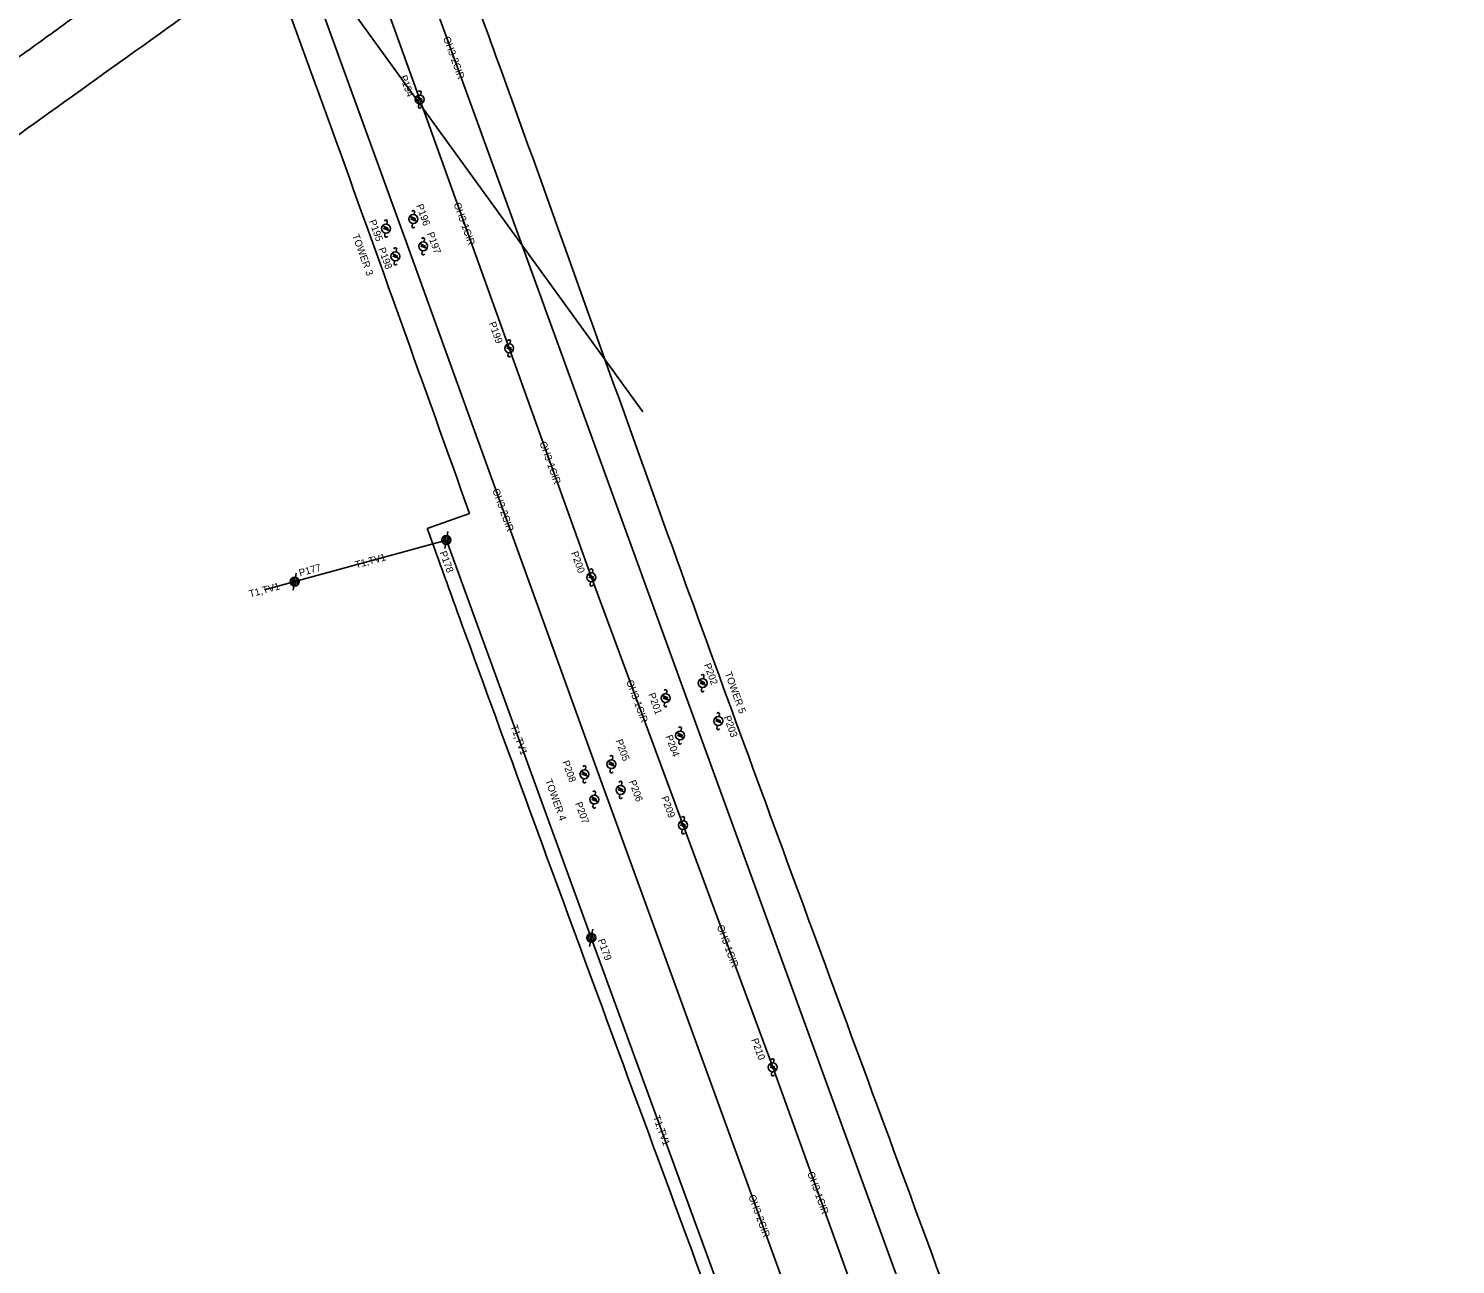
# Model space of a CAD drawing. Extents: x 1991878 to 2008544, y 770238 to 1141211.
# Drawn here: x 2004177 to 2004972, y 1138328 to 1139018 of the extents above; entities that cross this region are included whole.
import ezdxf

# ---------------------------------------------------------------- set-up
doc = ezdxf.new("R2010")
doc.units = 0
for name, color, linetype in [('RD_EX_SU_Ovhd', 7, 'Continuous'), ('RD_EX_SU_Pole', 7, 'Continuous'), ('RD_EX_SU_SwpLmt', 7, 'Continuous'), ('RD_EX_SU_TX_Ovhd', 7, 'Continuous'), ('RD_EX_SU_TX_Pole', 7, 'Continuous'), ('RD_HC_Cl', 7, 'Continuous')]:
    doc.layers.add(name, color=color, linetype=linetype)

msp = doc.modelspace()

# ---------------------------------------------------------------- linework, layer by layer
at = {"layer": 'RD_EX_SU_Ovhd'}
for p, q in [((2004386.44, 1138901.38), (2004185.77, 1139454.37)), ((2004282.2, 1139364.47), (2004545.93, 1138638.38)), ((2004354.72, 1139090.45), (2004394.96, 1138978.21)), ((2004394.96, 1138978.21), (2004444.8, 1138839.43)), ((2004496.56, 1138596.92), (2004386.44, 1138901.38)), ((2004444.8, 1138839.43), (2004490.68, 1138711.64)), ((2004325.26, 1138709.33), (2004409.79, 1138732.48)), ((2004409.79, 1138732.48), (2004490.53, 1138510.63)), ((2004308.35, 1138704.69), (2004325.26, 1138709.33)), ((2004490.68, 1138711.64), (2004541.77, 1138573.46)), ((2004545.93, 1138638.38), (2004819.62, 1137885.66)), ((2004672.08, 1138113.86), (2004496.56, 1138596.92)), ((2004541.77, 1138573.46), (2004591.73, 1138438.41)), ((2004490.53, 1138510.63), (2004568.62, 1138296.79)), ((2004591.73, 1138438.41), (2004642.44, 1138298.1))]:
    msp.add_line(p, q, dxfattribs=at)
at = {"layer": 'RD_EX_SU_Pole'}
for p, q in [((2004395.41, 1138980.66), (2004395.67, 1138982.14)), ((2004394.24, 1138974.27), (2004394.51, 1138975.75)), ((2004391.79, 1138913.93), (2004392.06, 1138915.41)), ((2004376.57, 1138908.67), (2004376.84, 1138910.15)), ((2004390.63, 1138907.54), (2004390.89, 1138909.02)), ((2004375.41, 1138902.28), (2004375.68, 1138903.75)), ((2004397.3, 1138898.77), (2004397.57, 1138900.25)), ((2004381.77, 1138893.17), (2004382.04, 1138894.65)), ((2004396.14, 1138892.37), (2004396.4, 1138893.85)), ((2004380.61, 1138886.78), (2004380.88, 1138888.25)), ((2004445.25, 1138841.89), (2004445.52, 1138843.36)), ((2004444.09, 1138835.49), (2004444.36, 1138836.97)), ((2004407.94, 1138730.8), (2004408.65, 1138734.71)), ((2004408.84, 1138730.17), (2004409.72, 1138734.98)), ((2004409.82, 1138729.98), (2004410.7, 1138734.81)), ((2004410.24, 1138734.95), (2004410.66, 1138737.25)), ((2004410.89, 1138730.23), (2004411.61, 1138734.2)), ((2004412.17, 1138731.72), (2004412.29, 1138732.36)), ((2004408.92, 1138727.72), (2004409.34, 1138730.02)), ((2004491.13, 1138714.1), (2004491.39, 1138715.57)), ((2004323.41, 1138707.64), (2004324.12, 1138711.55)), ((2004324.31, 1138707.01), (2004325.18, 1138711.83)), ((2004325.29, 1138706.83), (2004326.17, 1138711.66)), ((2004325.71, 1138711.79), (2004326.12, 1138714.09)), ((2004326.35, 1138707.08), (2004327.08, 1138711.05)), ((2004327.64, 1138708.56), (2004327.76, 1138709.2)), ((2004489.96, 1138707.7), (2004490.23, 1138709.18)), ((2004324.39, 1138704.56), (2004324.81, 1138706.87)), ((2004553.13, 1138655.14), (2004553.4, 1138656.62)), ((2004532.44, 1138646.77), (2004532.71, 1138648.24)), ((2004551.97, 1138648.74), (2004552.23, 1138650.22)), ((2004531.28, 1138640.37), (2004531.55, 1138641.85)), ((2004560.64, 1138627.58), (2004560.91, 1138629.06)), ((2004561.8, 1138633.98), (2004562.07, 1138635.45)), ((2004539.39, 1138619.54), (2004539.66, 1138621.02)), ((2004540.56, 1138625.94), (2004540.82, 1138627.41)), ((2004487.24, 1138604.34), (2004487.51, 1138605.81)), ((2004501.11, 1138603.54), (2004501.38, 1138605.02)), ((2004502.28, 1138609.94), (2004502.54, 1138611.41)), ((2004486.08, 1138597.94), (2004486.34, 1138599.42)), ((2004507.42, 1138595.59), (2004507.69, 1138597.07)), ((2004492.67, 1138590.23), (2004492.94, 1138591.7)), ((2004506.25, 1138589.2), (2004506.52, 1138590.67)), ((2004491.51, 1138583.83), (2004491.77, 1138585.31)), ((2004542.22, 1138575.92), (2004542.48, 1138577.39)), ((2004541.05, 1138569.52), (2004541.32, 1138571)), ((2004488.68, 1138508.94), (2004489.4, 1138512.86)), ((2004489.59, 1138508.31), (2004490.46, 1138513.13)), ((2004490.57, 1138508.13), (2004491.45, 1138512.96)), ((2004490.98, 1138513.09), (2004491.4, 1138515.39)), ((2004491.63, 1138508.38), (2004492.35, 1138512.35)), ((2004492.92, 1138509.86), (2004493.03, 1138510.51)), ((2004489.67, 1138505.86), (2004490.09, 1138508.17)), ((2004592.18, 1138440.87), (2004592.45, 1138442.34)), ((2004591.02, 1138434.47), (2004591.28, 1138435.95))]:
    msp.add_line(p, q, dxfattribs=at)
for points in [[(2004393.49, 1138979.63), (2004395.32, 1138978.45), (2004393.66, 1138978.28), (2004396.73, 1138977.14), (2004396.73, 1138977.14), (2004394.55, 1138978.18), (2004396.14, 1138978.31)], [(2004374.65, 1138907.64), (2004376.48, 1138906.45), (2004374.83, 1138906.28), (2004377.9, 1138905.14), (2004377.9, 1138905.14), (2004375.71, 1138906.19), (2004377.31, 1138906.31)], [(2004389.87, 1138912.9), (2004391.7, 1138911.72), (2004390.04, 1138911.55), (2004393.11, 1138910.41), (2004393.11, 1138910.41), (2004390.93, 1138911.45), (2004392.53, 1138911.58)], [(2004379.86, 1138892.14), (2004381.69, 1138890.96), (2004380.03, 1138890.79), (2004383.1, 1138889.65), (2004383.1, 1138889.65), (2004380.92, 1138890.69), (2004382.51, 1138890.82)], [(2004395.38, 1138897.74), (2004397.21, 1138896.55), (2004395.55, 1138896.38), (2004398.62, 1138895.24), (2004398.62, 1138895.24), (2004396.44, 1138896.28), (2004398.04, 1138896.41)], [(2004443.33, 1138840.86), (2004445.16, 1138839.67), (2004443.51, 1138839.5), (2004446.58, 1138838.36), (2004446.58, 1138838.36), (2004444.39, 1138839.4), (2004445.99, 1138839.53)], [(2004489.21, 1138713.06), (2004491.04, 1138711.88), (2004489.38, 1138711.71), (2004492.45, 1138710.57), (2004492.45, 1138710.57), (2004490.27, 1138711.61), (2004491.86, 1138711.74)], [(2004551.21, 1138654.11), (2004553.04, 1138652.92), (2004551.38, 1138652.75), (2004554.45, 1138651.61), (2004554.45, 1138651.61), (2004552.27, 1138652.65), (2004553.87, 1138652.78)], [(2004530.53, 1138645.73), (2004532.35, 1138644.55), (2004530.7, 1138644.38), (2004533.77, 1138643.24), (2004533.77, 1138643.24), (2004531.59, 1138644.28), (2004533.18, 1138644.41)], [(2004559.89, 1138632.94), (2004561.71, 1138631.76), (2004560.06, 1138631.59), (2004563.13, 1138630.45), (2004563.13, 1138630.45), (2004560.95, 1138631.49), (2004562.54, 1138631.62)], [(2004538.64, 1138624.9), (2004540.47, 1138623.72), (2004538.81, 1138623.55), (2004541.88, 1138622.41), (2004541.88, 1138622.41), (2004539.7, 1138623.45), (2004541.29, 1138623.58)], [(2004500.36, 1138608.91), (2004502.19, 1138607.72), (2004500.53, 1138607.55), (2004503.6, 1138606.41), (2004503.6, 1138606.41), (2004501.42, 1138607.45), (2004503.01, 1138607.58)], [(2004485.32, 1138603.3), (2004487.15, 1138602.12), (2004485.49, 1138601.95), (2004488.56, 1138600.81), (2004488.56, 1138600.81), (2004486.38, 1138601.85), (2004487.98, 1138601.98)], [(2004490.75, 1138589.19), (2004492.58, 1138588.01), (2004490.92, 1138587.84), (2004493.99, 1138586.7), (2004493.99, 1138586.7), (2004491.81, 1138587.74), (2004493.41, 1138587.87)], [(2004505.5, 1138594.56), (2004507.33, 1138593.38), (2004505.67, 1138593.21), (2004508.74, 1138592.07), (2004508.74, 1138592.07), (2004506.56, 1138593.11), (2004508.15, 1138593.24)], [(2004540.3, 1138574.89), (2004542.13, 1138573.7), (2004540.47, 1138573.53), (2004543.54, 1138572.39), (2004543.54, 1138572.39), (2004541.36, 1138573.43), (2004542.95, 1138573.56)], [(2004590.26, 1138439.84), (2004592.09, 1138438.65), (2004590.43, 1138438.48), (2004593.5, 1138437.34), (2004593.5, 1138437.34), (2004591.32, 1138438.38), (2004592.92, 1138438.51)]]:
    msp.add_lwpolyline(points, close=True, dxfattribs=at)
for centre in [(2004394.96, 1138978.21), (2004376.12, 1138906.21), (2004391.34, 1138911.48), (2004396.85, 1138896.31), (2004381.33, 1138890.71), (2004444.8, 1138839.43), (2004409.79, 1138732.48), (2004325.26, 1138709.33), (2004490.68, 1138711.64), (2004552.68, 1138652.68), (2004531.99, 1138644.31), (2004561.36, 1138631.52), (2004540.11, 1138623.48), (2004486.79, 1138601.88), (2004501.83, 1138607.48), (2004492.22, 1138587.77), (2004506.97, 1138593.13), (2004541.77, 1138573.46), (2004490.54, 1138510.63), (2004591.73, 1138438.41)]:
    msp.add_circle(centre, 2.5, dxfattribs=at)
for centre, start, end in [((2004394.94, 1138982.27), 349.68899, 169.68899), ((2004394.98, 1138974.14), 169.68899, 349.68899), ((2004391.32, 1138915.54), 349.68899, 169.68899), ((2004376.1, 1138910.28), 349.68899, 169.68899), ((2004391.36, 1138907.41), 169.68899, 349.68899), ((2004376.14, 1138902.14), 169.68899, 349.68899), ((2004396.83, 1138900.38), 349.68899, 169.68899), ((2004381.31, 1138894.78), 349.68899, 169.68899), ((2004396.87, 1138892.24), 169.68899, 349.68899), ((2004381.35, 1138886.64), 169.68899, 349.68899), ((2004444.78, 1138843.5), 349.68899, 169.68899), ((2004444.82, 1138835.36), 169.68899, 349.68899), ((2004490.66, 1138715.71), 349.68899, 169.68899), ((2004490.7, 1138707.57), 169.68899, 349.68899), ((2004552.66, 1138656.75), 349.68899, 169.68899), ((2004531.97, 1138648.38), 349.68899, 169.68899), ((2004552.7, 1138648.61), 169.68899, 349.68899), ((2004532.02, 1138640.24), 169.68899, 349.68899), ((2004561.33, 1138635.59), 349.68899, 169.68899), ((2004540.09, 1138627.55), 349.68899, 169.68899), ((2004561.38, 1138627.45), 169.68899, 349.68899), ((2004501.81, 1138611.55), 349.68899, 169.68899), ((2004540.13, 1138619.41), 169.68899, 349.68899), ((2004486.77, 1138605.95), 349.68899, 169.68899), ((2004486.81, 1138597.81), 169.68899, 349.68899), ((2004501.85, 1138603.41), 169.68899, 349.68899), ((2004506.95, 1138597.2), 349.68899, 169.68899), ((2004492.2, 1138591.84), 349.68899, 169.68899), ((2004506.99, 1138589.06), 169.68899, 349.68899), ((2004492.24, 1138583.7), 169.68899, 349.68899), ((2004541.75, 1138577.53), 349.68899, 169.68899), ((2004541.79, 1138569.39), 169.68899, 349.68899), ((2004591.71, 1138442.48), 349.68899, 169.68899), ((2004591.75, 1138434.34), 169.68899, 349.68899)]:
    msp.add_arc(centre, 0.75, start, end, dxfattribs=at)
at = {"layer": 'RD_EX_SU_SwpLmt'}
msp.add_line((2004399.16, 1138738.86), (2004422.68, 1138747.32), dxfattribs=at)
for points in [[(2004394.78, 1139119.65), (2004440.28, 1138994.6), (2004535.99, 1138728.08), (2004687.71, 1138314.66), (2004781.55, 1138057.24), (2005017.8, 1137400.02), (2005029.38, 1137367.89)], [(2004310.69, 1139058.54), (2004346.25, 1138960.58), (2004422.68, 1138747.32)], [(2004399.16, 1138738.86), (2004418.49, 1138685.43), (2004570.31, 1138271.72), (2004623.34, 1138126.65)]]:
    msp.add_spline(points, degree=3, dxfattribs=at)
msp.add_open_spline([(2003904.13, 1138805.76), (2003963.45, 1138830.79), (2004071.64, 1138887.18), (2004169.39, 1138957.24), (2004278.15, 1139035.08), (2004310.69, 1139058.54)], degree=3, dxfattribs=at)
at = {"layer": 'RD_HC_Cl'}
msp.add_line((2004092.14, 1139394.06), (2004519.36, 1138803.91), dxfattribs=at)
msp.add_open_spline([(2002937.27, 1138556.06), (2003081.12, 1138596.24), (2003224.54, 1138636.27), (2003324.8, 1138664.72), (2003440.8, 1138697.76), (2003610.3, 1138743.13), (2003753.45, 1138782.34), (2003851.96, 1138815.09), (2003945.32, 1138855.48), (2004023.07, 1138899.74), (2004117.46, 1138962.96), (2004239.69, 1139051.13), (2004401.3, 1139168.16), (2004522.74, 1139256.47), (2004724.1, 1139402.13), (2005003.72, 1139590.96), (2005189.76, 1139724.82), (2005285.27, 1139787.25)], degree=2, dxfattribs=at)

# ---------------------------------------------------------------- texts
at = {"layer": 'RD_EX_SU_TX_Ovhd'}
for s, rotation, p in [('OH3-2CIR', 289.96176, (2004407.89, 1139012.57)), ('OH3-1CIR', 289.7567, (2004413.75, 1138919.98)), ('OH3-1CIR', 289.74761, (2004461.61, 1138786.7)), ('OH3-2CIR', 289.88549, (2004435.34, 1138760.3)), ('T1,TV1', 15.31999, (2004359.5, 1138716.63)), ('T1,TV1', 15.31999, (2004300.33, 1138700.42)), ('OH3-1CIR', 290.29126, (2004509.99, 1138653.65)), ('T1,TV1', 289.99919, (2004445.46, 1138628.64)), ('OH3-1CIR', 290.30205, (2004560.51, 1138517.04)), ('T1,TV1', 290.06098, (2004524.87, 1138410.78)), ('OH3-1CIR', 289.87106, (2004610.93, 1138379.41)), ('OH3-2CIR', 289.96843, (2004578.15, 1138366.53))]:
    msp.add_text(s, height=4, rotation=rotation, dxfattribs=at).set_placement(p)
at = {"layer": 'RD_EX_SU_TX_Pole'}
for s, rotation, p in [('P194', 289.72403, (2004383.85, 1138990.96)), ('P196', 289.94504, (2004392.89, 1138919.08)), ('P195', 289.96176, (2004366.57, 1138910.36)), ('TOWER 3', 289.88549, (2004357.21, 1138902.38)), ('P197', 289.88549, (2004398.94, 1138903.46)), ('P198', 289.96176, (2004371.78, 1138894.86)), ('P199', 289.7567, (2004433.39, 1138853.44)), ('P178', 289.99919, (2004405.97, 1138725.56)), ('P200', 289.74761, (2004479.22, 1138725.4)), ('P177', 15.31999, (2004328.18, 1138712.17)), ('P202', 289.96176, (2004553.33, 1138662.96)), ('TOWER 5', 289.98135, (2004564.94, 1138658.19)), ('P201', 289.96176, (2004522.26, 1138646.45)), ('P203', 289.98135, (2004564.36, 1138633.75)), ('P205', 289.88549, (2004504.08, 1138620.57)), ('P204', 289.98135, (2004531.91, 1138622.96)), ('P208', 289.88549, (2004474.31, 1138608.72)), ('TOWER 4', 289.96843, (2004464.77, 1138598.41)), ('P206', 289.96843, (2004511.51, 1138597.83)), ('P209', 290.29126, (2004529.53, 1138588.84)), ('P207', 289.96843, (2004481.5, 1138585.59)), ('P179', 289.99919, (2004494.13, 1138509.32)), ('P210', 290.30205, (2004579.7, 1138453.77))]:
    msp.add_text(s, height=4, rotation=rotation, dxfattribs=at).set_placement(p)

doc.saveas('drawing.dxf')
